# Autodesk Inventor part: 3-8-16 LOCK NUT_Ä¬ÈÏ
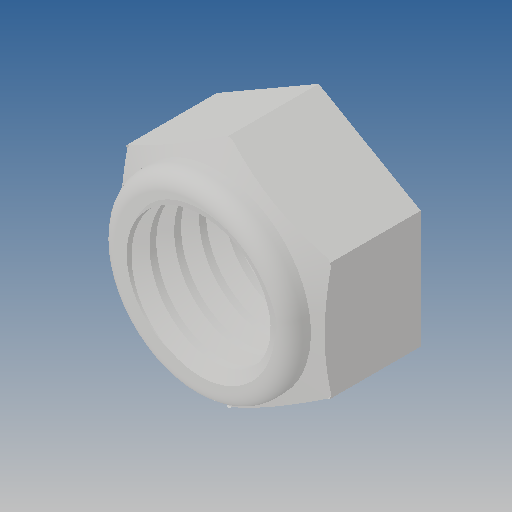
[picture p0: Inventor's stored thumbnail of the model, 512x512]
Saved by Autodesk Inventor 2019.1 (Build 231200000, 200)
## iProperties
Created: 2010-06
Part Number: 3-8-16 LOCK NUT_Ä¬ÈÏ
Material: Ogólny
Document SubType Name: Modeling
Designer: CADENGINEERING4
Density: 1 g/cm^3
Appearance: Domyślna
Author: CADENGINEERING4
Revision Number: ÈÎºÎ
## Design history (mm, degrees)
feature "NONE"
node "Bryła1"
